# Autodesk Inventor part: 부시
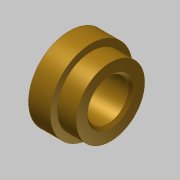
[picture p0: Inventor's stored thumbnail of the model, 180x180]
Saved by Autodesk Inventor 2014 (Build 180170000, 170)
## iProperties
Created: 2016-05
Part Number: 부시
Document SubType Name: Modeling
Designer: mduedu
Density: 7.86 g/cm^3
Material: 강철, 연강
Appearance: 황동 - 새틴
Author: mduedu
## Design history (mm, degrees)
sketch "스케치1"
  geometry: L1 (0, 0)-(15, 0); L2 (0, 7.5)-(15, 7.5); L3 (15, 7.5)-(15, 12.5); L4 (15, 12.5)-(8, 12.5); L5 (8, 12.5)-(8, 15); L6 (8, 15)-(0, 15); L7 (0, 15)-(0, 7.5)
  constraints: 14 end point, 4 parallel, 2 vertical alignment, 1 horizontal, 1 perpendicular, 1 vertical
  dimensions: "d0" = 15 distance of L1.start L1.end; "d1" = 15 diameter of L2 L1; "d2" = 25 diameter of L4 L1; "d3" = 8 distance of L5.end L6.end; "d4" = 30 diameter of L6 L1
revolve "회전1" sketch "스케치1" stored, may be unused: angle "d5" = 90 deg
chamfer "모따기1" distance "d6" = 1; stored, may be unused: second distance "d7" = 2, angle "d8" = 45 deg
node "솔리드1"
